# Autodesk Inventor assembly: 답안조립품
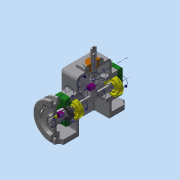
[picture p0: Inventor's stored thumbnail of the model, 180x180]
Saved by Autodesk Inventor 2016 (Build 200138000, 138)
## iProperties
Created: 2018-07
Part Number: 답안조립품
Material: 일반
Document SubType Name: Assembly
Designer: 2-
Author: 2-
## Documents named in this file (16)
- C:\Users\2-\Desktop\480708V1007\답안조립품.iam
- C:\Users\2-\Desktop\480708V1007\본체.ipt
- C:\Users\2-\Desktop\480708V1007\V벨트풀리.ipt
- C:\Users\2-\Desktop\480708V1007\베어링 12x32x10.ipt
- C:\Users\2-\Desktop\480708V1007\고정핀 1.2x8.ipt
- C:\Users\2-\Desktop\480708V1007\뒤커버.ipt
- C:\Users\2-\Desktop\480708V1007\링크.ipt
- C:\Users\2-\Desktop\480708V1007\멈춤나사 M3x8.ipt
- C:\Users\2-\Desktop\480708V1007\부시.ipt
- C:\Users\2-\Desktop\480708V1007\슬라이드.ipt
- C:\Users\2-\Desktop\480708V1007\앞커버.ipt
- C:\Users\2-\Desktop\480708V1007\오일 실 12 25 7.ipt
- C:\Users\2-\Desktop\480708V1007\키 4x4x10.ipt
- C:\Users\2-\Desktop\480708V1007\편심축.ipt
- C:\Users\2-\Desktop\480708V1007\핀 5x18.ipt
- C:\Users\2-\Desktop\480708V1007\볼트 M4.ipt
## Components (3 placed, 3 different names)
1. V벨트풀리:1 — 각도:1
2. 고정핀 1.2x8:1
3. 핀 5x18:1
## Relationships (1: Angle 1)
- 각도:1 [Angle]: V벨트풀리:1
